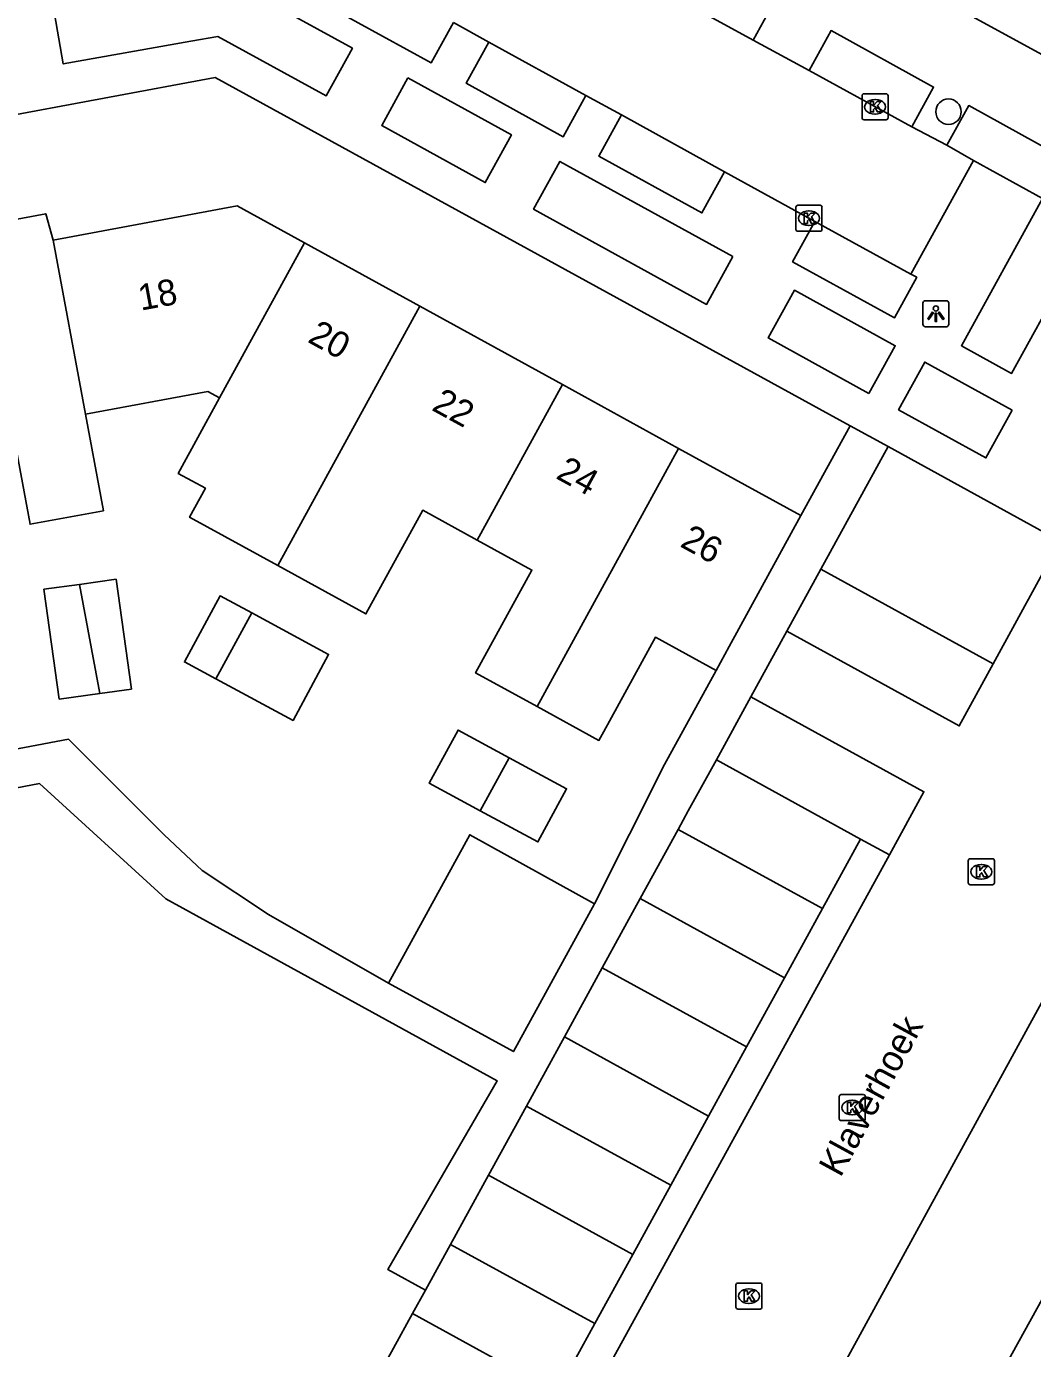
# Model space of a CAD drawing. Extents: x 158352 to 159489, y 383828 to 384597.
# Drawn here: x 158840.1 to 158878.7, y 384024.8 to 384075.6 of the extents above; entities that cross this region are included whole.
import ezdxf

# ---------------------------------------------------------------- set-up
doc = ezdxf.new("R2010")
doc.units = 0
for name, color, linetype in [('IMGEO_Boom', 7, 'Continuous'), ('IMGEO_Kolk', 7, 'Continuous'), ('IMGEO_Lichtpunt', 7, 'Continuous'), ('IMGEO_Openbare_ruimte_label', 7, 'Continuous'), ('IMGEO_Pand', 7, 'Continuous'), ('IMGEO_Pand_nummerreeks', 7, 'Continuous'), ('IMGEO_Rijbaan_lokaal_open', 7, 'Continuous'), ('IMGEO_Voetpad_open', 7, 'Continuous')]:
    doc.layers.add(name, color=color, linetype=linetype)

msp = doc.modelspace()

# ---------------------------------------------------------------- linework, layer by layer
at = {"layer": 'IMGEO_Boom'}
msp.add_circle((158875.504, 384072.293), 0.489, dxfattribs=at)
at = {"layer": 'IMGEO_Kolk'}
for p, q in [((158872.184, 384072.057), (158872.184, 384072.909)), ((158872.259, 384072.983), (158873.111, 384072.983)), ((158872.672, 384072.763), (158872.697, 384072.763)), ((158873.185, 384072.909), (158873.185, 384072.057)), ((158872.695, 384072.203), (158872.67, 384072.203)), ((158873.111, 384071.983), (158872.259, 384071.983)), ((158869.644, 384067.776), (158869.644, 384068.628)), ((158869.719, 384068.702), (158870.571, 384068.702)), ((158870.645, 384068.628), (158870.645, 384067.776)), ((158870.132, 384068.482), (158870.157, 384068.482)), ((158870.571, 384067.702), (158869.719, 384067.702)), ((158870.155, 384067.922), (158870.13, 384067.922)), ((158876.265, 384042.678), (158876.265, 384043.53)), ((158876.34, 384043.604), (158877.192, 384043.604)), ((158876.753, 384043.384), (158876.778, 384043.384)), ((158877.266, 384043.53), (158877.266, 384042.678)), ((158876.776, 384042.824), (158876.751, 384042.824)), ((158877.192, 384042.604), (158876.34, 384042.604)), ((158871.381, 384034.546), (158872.233, 384034.546)), ((158871.306, 384033.62), (158871.306, 384034.472)), ((158871.794, 384034.326), (158871.819, 384034.326)), ((158872.307, 384034.472), (158872.307, 384033.62)), ((158872.233, 384033.546), (158871.381, 384033.546)), ((158871.817, 384033.766), (158871.792, 384033.766)), ((158867.339, 384026.383), (158867.339, 384027.235)), ((158867.414, 384027.309), (158868.266, 384027.309)), ((158867.827, 384027.089), (158867.852, 384027.089)), ((158868.34, 384027.235), (158868.34, 384026.383)), ((158867.85, 384026.529), (158867.825, 384026.529)), ((158868.266, 384026.309), (158867.414, 384026.309))]:
    msp.add_line(p, q, dxfattribs=at)
for points in [[(158872.184, 384072.057), (158872.184, 384072.909)], [(158872.259, 384072.983), (158873.111, 384072.983)], [(158872.505, 384072.683), (158872.628, 384072.683), (158872.628, 384072.532), (158872.758, 384072.683), (158872.922, 384072.683), (158872.776, 384072.532), (158872.929, 384072.283), (158872.777, 384072.283), (158872.692, 384072.447), (158872.628, 384072.38), (158872.628, 384072.283), (158872.505, 384072.283), (158872.505, 384072.683)], [(158873.185, 384072.909), (158873.185, 384072.057)], [(158873.111, 384071.983), (158872.259, 384071.983)], [(158869.644, 384067.776), (158869.644, 384068.628)], [(158869.719, 384068.702), (158870.571, 384068.702)], [(158870.645, 384068.628), (158870.645, 384067.776)], [(158869.965, 384068.402), (158870.088, 384068.402), (158870.088, 384068.251), (158870.218, 384068.402), (158870.382, 384068.402), (158870.236, 384068.251), (158870.389, 384068.002), (158870.237, 384068.002), (158870.152, 384068.166), (158870.088, 384068.099), (158870.088, 384068.002), (158869.965, 384068.002), (158869.965, 384068.402)], [(158870.571, 384067.702), (158869.719, 384067.702)], [(158876.265, 384042.678), (158876.265, 384043.53)], [(158876.34, 384043.604), (158877.192, 384043.604)], [(158876.586, 384043.304), (158876.709, 384043.304), (158876.709, 384043.153), (158876.839, 384043.304), (158877.003, 384043.304), (158876.857, 384043.153), (158877.01, 384042.904), (158876.858, 384042.904), (158876.773, 384043.068), (158876.709, 384043.001), (158876.709, 384042.904), (158876.586, 384042.904), (158876.586, 384043.304)], [(158877.266, 384043.53), (158877.266, 384042.678)], [(158877.192, 384042.604), (158876.34, 384042.604)], [(158871.381, 384034.546), (158872.233, 384034.546)], [(158871.306, 384033.62), (158871.306, 384034.472)], [(158871.627, 384034.246), (158871.75, 384034.246), (158871.75, 384034.095), (158871.88, 384034.246), (158872.044, 384034.246), (158871.898, 384034.095), (158872.051, 384033.846), (158871.899, 384033.846), (158871.814, 384034.01), (158871.75, 384033.943), (158871.75, 384033.846), (158871.627, 384033.846), (158871.627, 384034.246)], [(158872.307, 384034.472), (158872.307, 384033.62)], [(158872.233, 384033.546), (158871.381, 384033.546)], [(158867.339, 384026.383), (158867.339, 384027.235)], [(158867.414, 384027.309), (158868.266, 384027.309)], [(158867.66, 384027.009), (158867.783, 384027.009), (158867.783, 384026.858), (158867.913, 384027.009), (158868.077, 384027.009), (158867.931, 384026.858), (158868.084, 384026.609), (158867.932, 384026.609), (158867.847, 384026.773), (158867.783, 384026.706), (158867.783, 384026.609), (158867.66, 384026.609), (158867.66, 384027.009)], [(158868.34, 384027.235), (158868.34, 384026.383)], [(158868.266, 384026.309), (158867.414, 384026.309)]]:
    msp.add_lwpolyline(points, dxfattribs=at)
for centre, start, end in [((158872.261, 384072.907), 91.552, 178.448), ((158872.261, 384072.907), 91.552, 178.448), ((158873.109, 384072.907), 1.552, 88.448), ((158873.109, 384072.907), 1.552, 88.448), ((158872.261, 384072.059), 181.552, 268.448), ((158872.261, 384072.059), 181.552, 268.448), ((158873.109, 384072.059), 271.552, 358.448), ((158873.109, 384072.059), 271.552, 358.448), ((158869.721, 384068.626), 91.552, 178.448), ((158869.721, 384068.626), 91.552, 178.448), ((158870.569, 384068.626), 1.552, 88.448), ((158870.569, 384068.626), 1.552, 88.448), ((158869.721, 384067.778), 181.552, 268.448), ((158869.721, 384067.778), 181.552, 268.448), ((158870.569, 384067.778), 271.552, 358.448), ((158870.569, 384067.778), 271.552, 358.448), ((158876.342, 384043.528), 91.552, 178.448), ((158876.342, 384043.528), 91.552, 178.448), ((158877.19, 384043.528), 1.552, 88.448), ((158877.19, 384043.528), 1.552, 88.448), ((158876.342, 384042.68), 181.552, 268.448), ((158876.342, 384042.68), 181.552, 268.448), ((158877.19, 384042.68), 271.552, 358.448), ((158877.19, 384042.68), 271.552, 358.448), ((158871.383, 384034.47), 91.552, 178.448), ((158871.383, 384034.47), 91.552, 178.448), ((158872.231, 384034.47), 1.552, 88.448), ((158872.231, 384034.47), 1.552, 88.448), ((158871.383, 384033.622), 181.552, 268.448), ((158871.383, 384033.622), 181.552, 268.448), ((158872.231, 384033.622), 271.552, 358.448), ((158872.231, 384033.622), 271.552, 358.448), ((158867.416, 384027.233), 91.552, 178.448), ((158867.416, 384027.233), 91.552, 178.448), ((158868.264, 384027.233), 1.552, 88.448), ((158868.264, 384027.233), 1.552, 88.448), ((158867.416, 384026.385), 181.552, 268.448), ((158867.416, 384026.385), 181.552, 268.448), ((158868.264, 384026.385), 271.552, 358.448), ((158868.264, 384026.385), 271.552, 358.448)]:
    msp.add_arc(centre, 0.0765, start, end, dxfattribs=at)
for centre, major_axis, ratio, start_param, end_param in [((158872.671, 384072.483), (-0.387, 0.002), 0.722429, 4.712389, 7.853982), ((158872.696, 384072.483), (-0.39, 0.002), 0.717154, 1.570796, 4.712389), ((158870.131, 384068.202), (-0.387, 0.002), 0.722429, 4.712389, 7.853982), ((158870.156, 384068.202), (-0.39, 0.002), 0.717154, 1.570796, 4.712389), ((158876.752, 384043.104), (-0.387, 0.002), 0.722429, 4.712389, 7.853982), ((158876.777, 384043.104), (-0.39, 0.002), 0.717154, 1.570796, 4.712389), ((158871.793, 384034.046), (-0.387, 0.002), 0.722429, 4.712389, 7.853982), ((158871.818, 384034.046), (-0.39, 0.002), 0.717154, 1.570796, 4.712389), ((158867.826, 384026.809), (-0.387, 0.002), 0.722429, 4.712389, 7.853982), ((158867.851, 384026.809), (-0.39, 0.002), 0.717154, 1.570796, 4.712389)]:
    msp.add_ellipse(centre, major_axis=major_axis, ratio=ratio, start_param=start_param, end_param=end_param, dxfattribs=at)
at = {"layer": 'IMGEO_Lichtpunt'}
for p, q in [((158875.423, 384065.034), (158874.615, 384065.034)), ((158875.423, 384065.034), (158874.615, 384065.034)), ((158874.521, 384064.939), (158874.521, 384064.132)), ((158874.521, 384064.939), (158874.521, 384064.132)), ((158875.517, 384064.132), (158875.517, 384064.939)), ((158875.517, 384064.132), (158875.517, 384064.939)), ((158874.615, 384064.038), (158875.423, 384064.038)), ((158874.615, 384064.038), (158875.423, 384064.038))]:
    msp.add_line(p, q, dxfattribs=at)
for points in [[(158874.895, 384064.603), (158874.934, 384064.575), (158874.746, 384064.313), (158874.708, 384064.34), (158874.895, 384064.603)], [(158874.997, 384064.555), (158875.044, 384064.555), (158875.044, 384064.233), (158874.997, 384064.233), (158874.997, 384064.555)], [(158875.107, 384064.575), (158875.145, 384064.602), (158875.332, 384064.34), (158875.293, 384064.312), (158875.107, 384064.575)]]:
    msp.add_lwpolyline(points, dxfattribs=at)
msp.add_circle((158875.02, 384064.737), 0.0994, dxfattribs=at)
for centre, start, end in [((158874.615, 384064.939), 90, 180), ((158874.615, 384064.939), 90, 180), ((158875.423, 384064.939), 0, 90), ((158875.423, 384064.939), 0, 90), ((158874.615, 384064.132), 180, 270), ((158874.615, 384064.132), 180, 270), ((158875.423, 384064.132), 270, 0), ((158875.423, 384064.132), 270, 360)]:
    msp.add_arc(centre, 0.0946, start, end, dxfattribs=at)
at = {"layer": 'IMGEO_Pand'}
for points in [[(158835.581, 384068.16), (158838.69, 384068.737), (158838.826, 384068.003), (158840.831, 384068.375), (158841.114, 384067.363)], [(158841.114, 384067.363), (158848.181, 384068.675), (158850.766, 384067.256)], [(158841.114, 384067.363), (158842.355, 384060.674)], [(158847.507, 384061.306), (158850.766, 384067.256)], [(158850.766, 384067.256), (158855.199, 384064.822)], [(158855.199, 384064.822), (158849.742, 384054.861)], [(158855.199, 384064.822), (158860.678, 384061.813)], [(158847.507, 384061.306), (158847.05, 384061.546), (158842.355, 384060.674)], [(158860.678, 384061.813), (158857.406, 384055.839)], [(158860.678, 384061.813), (158865.138, 384059.365)], [(158849.742, 384054.861), (158846.354, 384056.717), (158846.964, 384057.831), (158845.918, 384058.404), (158847.507, 384061.306)], [(158842.355, 384060.674), (158843.042, 384056.971), (158840.23, 384056.449), (158839.537, 384060.182), (158837.144, 384059.738)], [(158865.138, 384059.365), (158859.706, 384049.447)], [(158869.838, 384056.784), (158865.138, 384059.365)], [(158857.406, 384055.839), (158855.311, 384056.987), (158853.13, 384053.005), (158849.742, 384054.861)], [(158866.579, 384050.835), (158867.082, 384051.752), (158869.838, 384056.784)], [(158859.706, 384049.447), (158857.339, 384050.743), (158859.501, 384054.692), (158857.406, 384055.839)], [(158842.124, 384054.142), (158843.534, 384054.338), (158844.12, 384050.121), (158842.902, 384049.952)], [(158870.6, 384054.723), (158869.294, 384052.343)], [(158870.6, 384054.723), (158877.226, 384051.087)], [(158842.902, 384049.952), (158841.346, 384049.735), (158840.76, 384053.952), (158842.124, 384054.142)], [(158842.902, 384049.952), (158842.124, 384054.142)], [(158847.361, 384050.516), (158846.158, 384051.166), (158847.527, 384053.701), (158848.746, 384053.043)], [(158848.746, 384053.043), (158847.361, 384050.516)], [(158848.746, 384053.043), (158851.696, 384051.45), (158850.327, 384048.915), (158847.361, 384050.516)], [(158869.294, 384052.343), (158875.92, 384048.707), (158877.226, 384051.087)], [(158859.706, 384049.447), (158862.074, 384048.15), (158862.264, 384048.497), (158864.244, 384052.113), (158866.579, 384050.835)], [(158867.916, 384049.821), (158866.587, 384047.4)], [(158873.236, 384043.758), (158874.562, 384046.175), (158867.916, 384049.821)], [(158858.631, 384047.484), (158856.665, 384048.546), (158855.561, 384046.501), (158857.515, 384045.446)], [(158857.515, 384045.446), (158859.731, 384044.251), (158860.834, 384046.295), (158858.631, 384047.484)], [(158858.631, 384047.484), (158857.515, 384045.446)], [(158866.587, 384047.4), (158865.511, 384045.438), (158865.123, 384044.731)], [(158872.13, 384044.358), (158866.587, 384047.4)], [(158872.473, 384014.706), (158873.703, 384014.031), (158878.881, 384023.456), (158877.682, 384024.115), (158879.634, 384027.668), (158880.972, 384027.333), (158886.015, 384036.513), (158884.996, 384037.419), (158886.96, 384040.994), (158888.144, 384040.343), (158890.156, 384044.006), (158890.807, 384045.191), (158898.286, 384041.082), (158875.717, 384000), (158869.217, 383988.168), (158861.734, 383992.279), (158864.408, 383997.147), (158863.221, 383997.799), (158864.438, 384000), (158865.14, 384001.27), (158866.442, 384000.887), (158871.57, 384010.221), (158870.371, 384010.88), (158872.473, 384014.706)], [(158865.123, 384044.731), (158863.665, 384042.074)], [(158865.123, 384044.731), (158870.665, 384041.689)], [(158853.994, 384038.83), (158857.116, 384044.523), (158861.903, 384041.878)], [(158872.13, 384044.358), (158870.665, 384041.689)], [(158873.236, 384043.758), (158872.13, 384044.358)], [(158853.994, 384038.83), (158858.79, 384036.201), (158861.903, 384041.878)], [(158863.665, 384042.074), (158862.207, 384039.418)], [(158869.208, 384039.033), (158863.665, 384042.074)], [(158870.665, 384041.689), (158869.208, 384039.033)], [(158862.207, 384039.418), (158860.75, 384036.762)], [(158862.207, 384039.418), (158867.75, 384036.376)], [(158869.208, 384039.033), (158867.75, 384036.376)], [(158860.75, 384036.762), (158859.292, 384034.105)], [(158866.292, 384033.72), (158860.75, 384036.762)], [(158867.75, 384036.376), (158866.292, 384033.72)], [(158859.292, 384034.105), (158857.834, 384031.449)], [(158859.292, 384034.105), (158864.835, 384031.064)], [(158866.292, 384033.72), (158864.835, 384031.064)], [(158857.834, 384031.449), (158856.376, 384028.793)], [(158863.377, 384028.407), (158857.834, 384031.449)], [(158864.835, 384031.064), (158863.377, 384028.407)], [(158856.376, 384028.793), (158855.413, 384027.037)], [(158861.919, 384025.751), (158856.376, 384028.793)], [(158863.377, 384028.407), (158861.919, 384025.751)], [(158854.919, 384026.136), (158855.413, 384027.037)], [(158853.461, 384023.48), (158854.919, 384026.136)], [(158854.919, 384026.136), (158860.461, 384023.095)], [(158861.919, 384025.751), (158860.461, 384023.095)]]:
    msp.add_lwpolyline(points, dxfattribs=at)
at = {"layer": 'IMGEO_Rijbaan_lokaal_open'}
for points in [[(158868.005, 384075.047), (158864.081, 384077.196)], [(158857.855, 384074.969), (158856.486, 384075.723)], [(158857.855, 384074.969), (158861.58, 384072.918)], [(158868.005, 384075.047), (158870.149, 384073.873)], [(158874.092, 384071.714), (158870.149, 384073.873)], [(158862.94, 384072.168), (158861.58, 384072.918)], [(158862.94, 384072.168), (158866.905, 384069.985)], [(158874.092, 384071.714), (158875.439, 384071.005)], [(158876.465, 384070.414), (158875.439, 384071.005)], [(158876.465, 384070.414), (158874.061, 384066.057)], [(158870.367, 384068.078), (158866.905, 384069.985)], [(158879.276, 384064.692), (158877.928, 384062.244), (158875.998, 384063.307), (158879.109, 384068.958)], [(158870.367, 384068.078), (158874.061, 384066.057)], [(158877.226, 384051.087), (158879.798, 384055.802)], [(158867.916, 384049.821), (158869.294, 384052.343)], [(158886.706, 384052.025), (158861.185, 384005.358), (158854.263, 384009.207), (158873.236, 384043.758)]]:
    msp.add_lwpolyline(points, dxfattribs=at)
at = {"layer": 'IMGEO_Voetpad_open'}
for points in [[(158866.975, 384081.108), (158906.994, 384059.275)], [(158864.081, 384077.196), (158864.933, 384078.743), (158868.852, 384076.584), (158868.005, 384075.047)], [(158856.486, 384075.723), (158855.628, 384074.165), (158851.896, 384076.22), (158852.754, 384077.778)], [(158848.008, 384077.264), (158845.207, 384076.768), (158841.164, 384076.052), (158841.504, 384074.132), (158846.398, 384074.998), (158847.446, 384075.184), (158851.596, 384072.898), (158852.606, 384074.732), (158848.008, 384077.264)], [(158870.149, 384073.873), (158870.994, 384075.408), (158874.932, 384073.24), (158874.092, 384071.714)], [(158861.58, 384072.918), (158860.707, 384071.334), (158856.982, 384073.385), (158857.855, 384074.969)], [(158871.727, 384060.229), (158847.335, 384073.606), (158838.799, 384072.022)], [(158854.741, 384073.591), (158853.733, 384071.759), (158857.71, 384069.569), (158858.718, 384071.401), (158854.741, 384073.591)], [(158866.905, 384069.985), (158866.034, 384068.405), (158862.07, 384070.588), (158862.94, 384072.168)], [(158875.439, 384071.005), (158876.28, 384072.532), (158880.245, 384070.349), (158879.401, 384068.815)], [(158867.221, 384066.727), (158860.58, 384070.384), (158859.57, 384068.551), (158866.212, 384064.894), (158867.221, 384066.727)], [(158879.109, 384068.958), (158876.465, 384070.414)], [(158874.061, 384066.057), (158874.285, 384065.934), (158873.426, 384064.374), (158869.514, 384066.529), (158870.367, 384068.078)], [(158872.45, 384061.472), (158868.578, 384063.605), (158869.587, 384065.438), (158873.46, 384063.305), (158872.45, 384061.472)], [(158877.949, 384060.833), (158876.939, 384059), (158873.586, 384060.847), (158874.595, 384062.68), (158877.949, 384060.833)], [(158869.838, 384056.784), (158871.727, 384060.229)], [(158871.727, 384060.229), (158873.182, 384059.431)], [(158873.182, 384059.431), (158870.6, 384054.723)], [(158879.798, 384055.802), (158873.182, 384059.431)], [(158861.903, 384041.878), (158864.598, 384047.218), (158866.579, 384050.835)], [(158814.18, 384042.98), (158841.707, 384048.193), (158842.065, 384047.835), (158845.377, 384044.525), (158846.844, 384043.153), (158849.388, 384041.463), (158853.994, 384038.83)], [(158855.413, 384027.037), (158853.974, 384027.826), (158858.17, 384035.07), (158845.444, 384042.068), (158840.594, 384046.49), (158821.53, 384042.846)]]:
    msp.add_lwpolyline(points, dxfattribs=at)

# ---------------------------------------------------------------- texts
at = {"layer": 'IMGEO_Openbare_ruimte_label'}
msp.add_text('Klaverhoek', height=1, rotation=61.385, dxfattribs=at).set_placement((158871.355, 384031.333))
at = {"layer": 'IMGEO_Pand_nummerreeks'}
for s, rotation, p in [('18', 10.5167, (158844.48, 384064.651)), ('20', 331.2298, (158850.849, 384063.468)), ('22', 331.2298, (158855.612, 384060.853)), ('24', 331.2298, (158860.383, 384058.233)), ('26', 331.2318, (158865.151, 384055.616))]:
    msp.add_text(s, height=1, rotation=rotation, dxfattribs=at).set_placement(p)

doc.saveas('drawing.dxf')
